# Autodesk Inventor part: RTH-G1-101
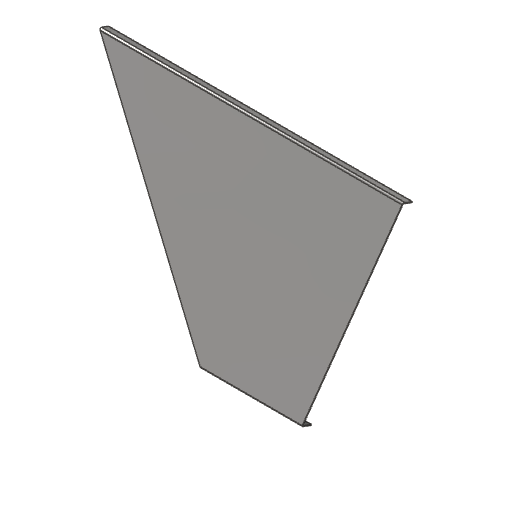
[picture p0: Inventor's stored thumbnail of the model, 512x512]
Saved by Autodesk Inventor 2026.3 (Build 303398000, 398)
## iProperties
Created: 2026-09
Part Number: RTH-G1-101
Material: Steel, Mild
Document SubType Name: Sheet Metal
Designer: mykol
Density: 7.85 g/cm^3
Sheet Metal Rule: Default_mm
Appearance: Semi-Polished
Project: RTH-G1
Description: PANEL Y- 3 CS FORMED FLANGES
Stock Number: PL 3 x 1200 x 1040
Mass: 19425 g
Surface Area: 16611.6 cm^2
Volume: 2474.52 cm^3
Flat Pattern Width: 103.348 cm
Flat Pattern Length: 120 cm
Flat Pattern Area: 12401.8 cm^2
Sheet Metal Width: 1033.481 mm
Sheet Metal Length: 1200.000 mm
Sheet Metal Area: 1240177.359 mm^2
RuthenClass: Fabricated
Thickness: 3
RuthenConfigId: RTH-G1-A-b1a1fe2e
RuthenRuleSet: 1.0.0
RuthenAddInVersion: 1.0.0
Author: mykol
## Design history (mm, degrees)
node "Face1"
  sketch "Sketch1"
    geometry: L1 (-200, 0)-(200, 0); L2 (200, 0)-(600, 965.66); L3 (600, 965.66)-(-600, 965.66); L4 (-600, 965.66)-(-200, 0)
    constraints: 8 end point
node "Flange1"
node "Flange2"
body "Solid1"
face "Plate1" dims "d0" = 3 (= Thickness)
sketch "Sketch2"
  geometry: L1 through (600, 0) direction (-1, 0); L2 through (0, -20) direction (0, -1); L3 (0, -40)-(1200, -40); L4 (1200, -40)-(1200, 0)
  constraints: 6 end point, 1 horizontal, 1 perpendicular, 1 vertical
face "Plate2" dims "d0" = 3 (= Thickness), "d1" = 3 (= Thickness), "d2" = 1.5 (= 0.5 x Thickness), "d3" = 6 (= 2 x Thickness), "d4" = 3 (= Thickness), "d5" = 40, "d6" = 19.41688, "d7" = 3 (= Thickness), "d8" = 12 (= 4 x Thickness), "d9" = 0.5, "d10" = 3 (= JacobiRadiusSize), "SeamGap" = 0.01
bend "Bend1" dims "d0" = 3 (= Thickness), "d1" = 3 (= Thickness), "d2" = 1.5 (= 0.5 x Thickness), "d3" = 6 (= 2 x Thickness), "d4" = 3 (= Thickness), "d5" = 40, "d6" = 19.41688, "d7" = 3 (= Thickness), "SeamGap" = 0.01
feature "Corner1" dims "d5" = 40, "d6" = 19.41688, "d8" = 12 (= 4 x Thickness), "d9" = 0.5, "d10" = 3 (= JacobiRadiusSize)
sketch "Sketch3"
  geometry: L1 through (200, 0) direction (-1, 0); L2 through (0, -20) direction (0, -1); L3 (0, -40)-(400, -40); L4 (400, -40)-(400, 0)
  constraints: 6 end point, 1 horizontal, 1 perpendicular, 1 vertical
face "Plate3" dims "d0" = 3 (= Thickness), "d11" = 3 (= Thickness), "d12" = 1.5 (= 0.5 x Thickness), "d13" = 6 (= 2 x Thickness), "d14" = 3 (= Thickness), "d15" = 40, "d16" = 11.99905, "d17" = 3 (= Thickness), "d18" = 12 (= 4 x Thickness), "d19" = 0.5, "d20" = 3 (= JacobiRadiusSize), "SeamGap" = 0.01
bend "Bend2" dims "d0" = 3 (= Thickness), "d11" = 3 (= Thickness), "d12" = 1.5 (= 0.5 x Thickness), "d13" = 6 (= 2 x Thickness), "d14" = 3 (= Thickness), "d15" = 40, "d16" = 11.99905, "d17" = 3 (= Thickness), "SeamGap" = 0.01
feature "Corner2" dims "d15" = 40, "d16" = 11.99905, "d18" = 12 (= 4 x Thickness), "d19" = 0.5, "d20" = 3 (= JacobiRadiusSize)
feature "Definition1"
other parameters: "Thickness" = 3, "BendRadius" = 3 (= Thickness), "BendReliefWidth" = 3 (= Thickness), "BendReliefDepth" = 1.5 (= 0.5 x Thickness), "CornerReliefSize" = 12 (= 4 x Thickness), "MinimumRemnant" = 6 (= 2 x Thickness), "TransitionRadius" = 3 (= BendRadius), "JacobiRadiusSize" = 3 (= BendRadius), "GapSize" = 3 (= Thickness), "BendRadius" = 3, "BendReliefDepth" = 1.5, "BendReliefWidth" = 3, "CornerReliefSize" = 12, "GapSize" = 3, "JacobiRadiusSize" = 3, "MinimumRemnant" = 6, "Thickness" = 3, "TransitionRadius" = 3
